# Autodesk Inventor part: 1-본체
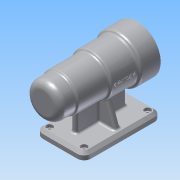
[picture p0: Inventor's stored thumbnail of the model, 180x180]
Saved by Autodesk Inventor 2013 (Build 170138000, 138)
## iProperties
Created: 2016-06
Part Number: 1-본체
Material: 알루미늄 6061
Document SubType Name: Modeling
Designer: Administrator
Density: 2.71 g/cm^3
Mass: 674.634 g
Surface Area: 646.752 cm^2
Volume: 248.942 cm^3
Author: Administrator
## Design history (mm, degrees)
sketch "스케치1"
  geometry: C1 r 25 at (0, 0); 1 further point
  constraints: 1 centre point, 1 coincident
  dimensions: "d0" = 50 diameter of C1
extrude "돌출1" new body sketch "스케치1" distance "d2" = 25; taper "d3" = 0 deg
sketch "스케치2"
  geometry: C1 r 25 at (0, 0) reference; C2 r 27 at (0, 0)
  constraints: 1 centre point, 1 coincident
  dimensions: "d4" = 54 diameter of C2
extrude "돌출2" join sketch "스케치2" distance "d6" = 45; taper "d7" = 0 deg
sketch "스케치3"
  geometry: C1 r 27 at (0, 0) reference; C2 r 30 at (0, 0)
  constraints: 1 centre point, 1 coincident
  dimensions: "d8" = 60 diameter of C2
extrude "돌출3" join sketch "스케치3" distance "d10" = 39; taper "d11" = 0 deg
sketch "스케치4"
  geometry: C1 r 30 at (0, 0) reference; C2 r 34 at (0, 0)
  constraints: 1 centre point, 1 coincident
  dimensions: "d12" = 68 diameter of C2
extrude "돌출4" join sketch "스케치4" distance "d14" = 28; taper "d15" = 0 deg
node "작업 평면1"
sketch "스케치5"
  geometry: L1 (-35, 0)-(35, 0); L2 (35, 0)-(35, -112); L3 (35, -112)-(-35, -112); L4 (-35, -112)-(-35, 0); L5 (25, 25)-(-25, 25) reference; L6 (-34, -112)-(34, -112) reference; 3 further points
  constraints: 8 end point, 2 midpoint, 2 parallel, 1 horizontal, 1 horizontal alignment, 1 perpendicular, 1 vertical alignment
  dimensions: "d17" = 112 distance of L1.end L2.end; "d19" = 70 distance of L1.start L1.end
extrude "돌출5" join sketch "스케치5" distance "d20" = 10; taper "d21" = 0 deg
sketch "스케치6"
  geometry: L1 (-35, 0)-(35, 0) reference; L2 (35, 112)-(-35, 112) reference; L3 (-35, 112)-(-35, 0) reference; L4 (-4, 20)-(4, 20); L5 (4, 20)-(4, 92); L6 (4, 92)-(-4, 92); L7 (-4, 92)-(-4, 20); 5 further points
  constraints: 8 end point, 4 midpoint, 2 parallel, 1 horizontal, 1 horizontal alignment, 1 perpendicular, 1 vertical alignment
  dimensions: "d22" = 8 distance between parallel lines of L5 L7; "d24" = 20 distance between parallel lines of L2 L6
extrude "돌출6" join sketch "스케치6" stored distance "d25" = 10; taper "d26" = 0 deg
node "작업 평면2"
sketch "스케치7"
  geometry: L1 (39, 0)-(-31, 0) reference; L2 (-24, 0)-(-11.509, 34.32); L3 (-31, -10)-(-31, 0) reference; A1 r 30 centre (4, 60) between (8, 30.268) and (0, 30.268) reference; 1 further point
  constraints: 2 end point, 1 point on circle, 1 point on line
  dimensions: "d27" = 7 distance from line of L3 L2.start; "d29" = 110 deg angle of L2 L1
feature "리브1" sketch "스케치7" dims "d30" = 1, "d31" = 8, "d32" = 0, "d33" = 0, "d34" = 1, "d35" = 1
sketch "스케치8"
  geometry: L1 (39, 0)-(-31, 0) reference; L2 (32, 0)-(19.509, 34.32); L3 (39, -10)-(39, 0) reference; A1 r 30 centre (4, 60) between (8, 30.268) and (0, 30.268) reference; 1 further point
  constraints: 2 end point, 1 point on circle, 1 point on line
  dimensions: "d36" = 7 distance from line of L3 L2.start; "d37" = 110 deg angle of L1 L2
feature "리브2" sketch "스케치8" dims "d38" = 1, "d39" = 8, "d40" = 0, "d41" = 0, "d42" = 1, "d43" = 1
sketch "스케치9"
  geometry: C1 r 34 at (0, 0) reference; C2 r 21 at (0, 0)
  constraints: 1 centre point, 1 coincident
  dimensions: "d44" = 42 diameter of C2
extrude "돌출7" cut sketch "스케치9" distance "d46" = 15; taper "d47" = 0 deg
sketch "스케치10"
  geometry: C1 r 21 at (0, 0) reference; C2 r 24 at (0, 0)
  constraints: 1 centre point, 1 coincident
  dimensions: "d48" = 48 diameter of C2
extrude "돌출8" cut sketch "스케치10" distance "d50" = 54; taper "d51" = 0 deg
sketch "스케치11"
  geometry: C1 r 24 at (0, 0) reference; C2 r 21 at (0, 0)
  constraints: 1 centre point, 1 coincident
  dimensions: "d52" = 42 diameter of C2
extrude "돌출9" cut sketch "스케치11" distance "d54" = 12; taper "d55" = 0 deg
sketch "스케치12"
  geometry: C1 r 21 at (0, 0) reference; C2 r 17.5 at (0, 0)
  constraints: 1 centre point, 1 coincident
  dimensions: "d56" = 35 diameter of C2
extrude "돌출10" cut sketch "스케치12" distance "d58" = 18; taper "d59" = 0 deg
sketch "스케치13"
  geometry: C1 r 17.5 at (0, 0) reference; C2 r 16 at (0, 0)
  constraints: 1 centre point, 1 coincident
  dimensions: "d60" = 32 diameter of C2
extrude "돌출11" cut sketch "스케치13" distance "d62" = 4; taper "d63" = 0 deg
sketch "스케치14"
  geometry: C1 r 16 at (0, 0) reference; C2 r 10.5 at (0, 0)
  constraints: 1 centre point, 1 coincident
  dimensions: "d64" = 21 diameter of C2
extrude "돌출12" cut sketch "스케치14" distance "d66" = 3; taper "d67" = 0 deg
fillet "모깎기1" dims "d68" = 10
fillet "모깎기2" dims "d69" = 3
fillet "모깎기3" dims "d70" = 3
fillet "모깎기4" dims "d71" = 10
chamfer "모따기1" distance "d72" = 4; stored, may be unused: second distance "d73" = 2, angle "d74" = 45 deg
sketch "스케치15"
  geometry: L1 (-31, 10)-(-31, 102) reference; L2 (25, 4)-(-25, 4) reference; C1 r 4.5 at (-25, 10); C2 r 4.5 at (25, 10); C3 r 4.5 at (-25, 102); C4 r 4.5 at (25, 102); 3 further points
  constraints: 4 centre point, 3 equal radius, 2 horizontal alignment, 2 midpoint, 2 vertical alignment
  dimensions: "d75" = 92 distance of C1.centre C3.centre; "d77" = 46 vertical distance of point (-31, 56) C3.centre; "d78" = 50 distance of C2.centre C1.centre; "d79" = 25 horizontal distance of point (0, 4) C2.centre; "d80" = 9 diameter of C3
extrude "돌출13" cut sketch "스케치15" distance "d81" = 4; taper "d82" = 0 deg
sketch "스케치16"
  geometry: C1 r 4.5 at (0, 0) reference; C2 r 2.5 at (0, 0); 1 further point
  constraints: 1 centre point, 1 coincident
  dimensions: "d83" = 5 diameter of C2
extrude "돌출14" cut sketch "스케치16" stored distance "d85" = 4; taper "d86" = 0 deg
sketch "스케치17"
  geometry: C1 r 4.5 at (0, 0) reference; C2 r 2.5 at (0, 0); 1 further point
  constraints: 1 centre point, 1 coincident
  dimensions: "d87" = 5 diameter of C2
extrude "돌출15" cut sketch "스케치17" distance "d89" = 7; taper "d90" = 0 deg
sketch "스케치18"
  geometry: C1 r 4.5 at (0, 0) reference; C2 r 2.5 at (0, 0); 1 further point
  constraints: 1 centre point, 1 coincident
  dimensions: "d91" = 5 diameter of C2
extrude "돌출16" cut sketch "스케치18" distance "d93" = 7; taper "d94" = 0 deg
sketch "스케치19"
  geometry: C1 r 4.5 at (0, 0) reference; C2 r 2.5 at (0, 0); 1 further point
  constraints: 1 centre point, 1 coincident
  dimensions: "d95" = 5 diameter of C2
extrude "돌출17" cut sketch "스케치19" distance "d97" = 7; taper "d98" = 0 deg
fillet "모깎기5" dims "d99" = 3
fillet "모깎기6" dims "d100" = 0.3
fillet "모깎기7" dims "d101" = 3
chamfer "모따기2" distance "d102" = 1; stored, may be unused: second distance "d103" = 2, angle "d104" = 45 deg
sketch "스케치20"
  geometry: C1 r 34 at (0, 0) reference; C2 r 22 at (0, 0) reference; A1 r 26 centre (0, 0) between (0, 26) and (-26, 0); 2 further points
  constraints: 4 point on circle, 2 horizontal alignment, 2 vertical alignment, 1 centre point, 1 coincident
  dimensions: "d105" = 52 diameter of A1
hole "구멍1" sketch "스케치20" at (0, 26), (-26, 0), (0, -26), (26, 0) diameter "d107" = 3.242; stored, may be unused: countersink angle "d111" = 90 deg, drill point angle "d113" = 118 deg; dims "d108" = 8, "d109" = 4, "d110" = 2, "d112" = 11
node "작업 평면3"
sketch "스케치21"
  geometry: L1 (-34, -67)-(34, -67) reference; 2 further points
  constraints: 1 vertical alignment, 1 other
  dimensions: "d114" = 48 distance from line of L1 point (0, -19)
feature "엠보싱1" sketch "스케치21" dims "d12" = 68, "d115" = 0.5, "d116" = 0
fillet "모깎기8" dims "d117" = 3
fillet "모깎기9" dims "d118" = 3
fillet "모깎기10" dims "d119" = 4
fillet "모깎기11" dims "d120" = 3
fillet "모깎기12" dims "d121" = 3
node "솔리드1"
